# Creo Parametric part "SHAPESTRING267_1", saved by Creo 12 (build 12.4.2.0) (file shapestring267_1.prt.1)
Units: Custom; MM, KILOGRAM, SECS

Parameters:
  PTC_WM_ITERATION = "0"
  PTC_WM_VERSION = "-.0"
  PTC_WM_LIFECYCLE_STATE = "In Work"
  PTC_WM_LIFECYCLE = "MO_CADDocument"
  PTC_WM_CREATED_BY = "Maximilian Roepper (Z0017RMS: MO)"
  PTC_WM_CREATED_ON = "18-Sep-26 11:36:42 AM"
  PTC_WM_MODIFIED_BY = "Maximilian Roepper (Z0017RMS: MO)"
  PTC_WM_MODIFIED_ON = "18-Sep-26 11:36:46 AM"
  PDMLINKNUMBER = "PDM000071454772"
  PTC_WM_NAME = "shapestring267_1.prt"
  PTC_WM_NUMBER = "PDM000071454772"

Other parameters: WEIGHT, WEIGHT_FACTOR, WEIGHT_ADD, _MASS_TEMP, _DIFF_TEMP, MC_ERRORS, SUPPLIER

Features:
  1. coordinate system
  2. datum plane "PRT_YZ"
  3. datum plane "PRT_XY"
  4. datum plane "PRT_XZ"
  5. coordinate system
  6. datum axis
  7. datum axis
  8. datum axis
  9. coordinate system
  10. imported feature
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
Other named items: PRT, SIEMENS_MO, DRW_VIEW_ORG, PRT_X, PRT_Y, PRT_Z, CS0, ROUGH_GROB

Layers: 00_STD_CSYS-KSYS, 01_STD_PLANES-EBENEN, 02_STD_AXES-ACHSEN, 03_STD_CSYS-KSYS, 24_IMPORT_FEAT-IMPORT_KE, WHITE

Surfaces: 1 plane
